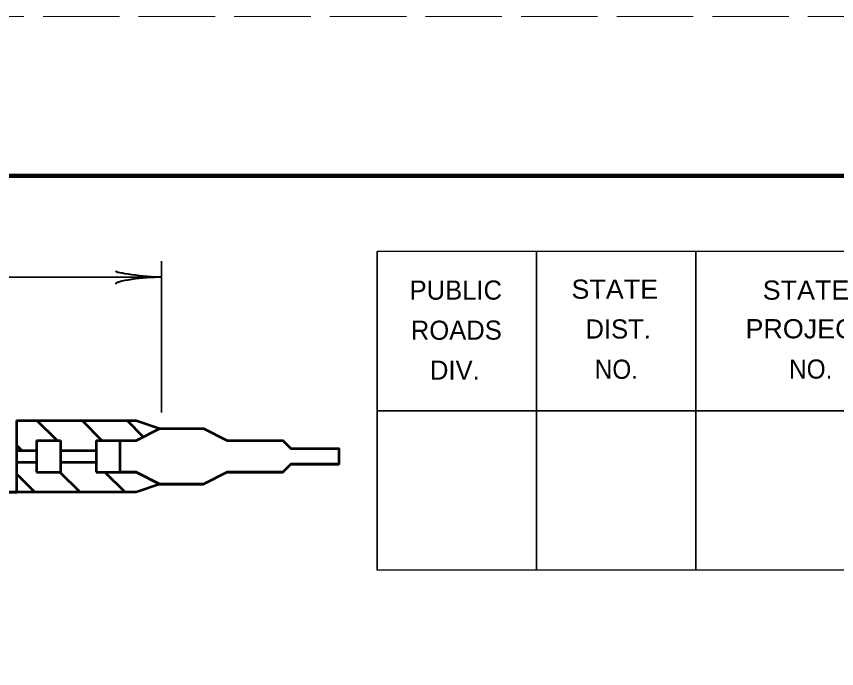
# Model space of a CAD drawing. Extents: x -1 to 679, y 0 to 440.
# Drawn here: x 531 to 582.5, y 399 to 439.9 of the extents above; entities that cross this region are included whole.
import ezdxf

# ---------------------------------------------------------------- set-up
doc = ezdxf.new("R2010")
doc.units = 0
doc.header["$LTSCALE"] = 0.8
doc.linetypes.add('LONG_DASHED', pattern=[7.5, 6, -1.5])
doc.layers.add('1', color=7, linetype='Continuous', lineweight=53)
doc.layers.add('61', color=7, linetype='Continuous', lineweight=35)

msp = doc.modelspace()

# ---------------------------------------------------------------- linework, layer by layer
at = {"layer": '1', "lineweight": 35}
for p, q in [((540.1397, 415.0423), (540.1397, 424.5423)), ((506.156, 423.5423), (540.1397, 423.5423))]:
    msp.add_line(p, q, dxfattribs=at)
at = {"layer": '1'}
for p, q in [((531.0403, 414.5423), (538.5534, 414.5423)), ((531.0497, 414.5423), (531.0497, 410.0423)), ((533.5727, 413.3044), (532.3348, 414.5423)), ((536.4132, 413.2923), (535.1632, 414.5423)), ((539.0078, 413.5261), (537.9916, 414.5423)), ((538.5534, 414.5423), (540.0372, 414.0423)), ((538.5534, 413.2982), (540.0372, 414.0423)), ((540.0372, 414.0423), (542.7872, 414.0423)), ((532.3034, 413.2982), (532.3034, 411.2982)), ((532.3034, 413.2982), (533.8034, 413.2982)), ((533.8034, 413.2982), (533.8034, 411.2982)), ((536.0534, 413.2982), (536.0534, 411.2982)), ((536.0534, 413.2982), (538.5534, 413.2982)), ((547.7709, 413.2982), (548.2709, 412.7982)), ((531.3755, 412.6732), (531.0481, 413.0006)), ((548.2709, 412.7982), (551.2709, 412.7982)), ((551.2709, 412.7982), (551.2709, 411.7982)), ((531.0497, 412.6732), (532.3034, 412.6732)), ((533.8034, 412.6732), (536.0534, 412.6732)), ((531.0497, 411.9232), (532.3034, 411.9232)), ((533.8034, 411.9232), (536.0534, 411.9232)), ((547.7709, 411.2982), (548.2709, 411.7982)), ((548.2709, 411.7982), (551.2709, 411.7982)), ((532.3034, 411.2982), (533.8034, 411.2982)), ((535.0358, 410.0423), (533.7726, 411.3055)), ((536.0534, 411.2982), (538.5534, 411.2982)), ((537.8643, 410.0423), (536.6142, 411.2923)), ((538.5534, 411.2982), (540.0372, 410.5423)), ((544.2709, 411.2982), (547.7709, 411.2982)), ((532.2073, 410.0423), (531.0571, 411.1927)), ((540.0372, 410.5423), (538.5534, 410.0423)), ((540.0372, 410.5423), (542.7872, 410.5423)), ((525.156, 410.0423), (531.0628, 410.0423)), ((538.5534, 410.0423), (531.0628, 410.0423))]:
    msp.add_line(p, q, dxfattribs=at)
msp.add_lwpolyline([(537.5534, 411.2982), (537.5534, 413.2982), (538.5534, 413.2982), (540.0372, 414.0423), (542.7872, 414.0423), (544.2709, 413.2982), (547.7709, 413.2982), (548.2709, 412.7982), (551.2709, 412.7982), (551.2709, 411.7982), (548.2709, 411.7982), (547.7709, 411.2982), (544.2709, 411.2982), (542.7872, 410.5423), (540.0372, 410.5423), (538.5534, 411.2982)], close=True, dxfattribs=at)
for points in [[(542.7872, 414.0423), (544.2709, 413.2982), (547.7709, 413.2982)], [(531.0628, 410.0423), (527.294, 410.0423), (527.294, 413.2981)]]:
    msp.add_lwpolyline(points, dxfattribs=at)
at = {"layer": '1', "lineweight": 40}
for centre, major_axis, ratio, start_param, end_param in [((539.0192, 423.7539), (1.7565, -0.1757), 0.07063, 3.1407148, 5.41811), ((539.0485, 423.266), (1.7857, 0.1562), 0.122415, 0.8963533, 3.1415927)]:
    msp.add_ellipse(centre, major_axis=major_axis, ratio=ratio, start_param=start_param, end_param=end_param, dxfattribs=at)
at = {"layer": '61', "linetype": 'LONG_DASHED', "lineweight": 13}
msp.add_line((-1.285, 439.9088), (678.735, 439.9088), dxfattribs=at)
at = {"layer": '61'}
for p, q in [((563.675, 425.1488), (563.675, 405.1488)), ((573.675, 425.1488), (573.675, 405.1488)), ((661.675, 415.1288), (553.655, 415.1488))]:
    msp.add_line(p, q, dxfattribs=at)
at = {"layer": '61', "lineweight": 158}
msp.add_lwpolyline([(667.755, 429.9088), (28.715, 429.9088), (28.715, 9.8888)], dxfattribs=at)
at = {"layer": '61'}
for points in [[(661.655, 425.1688), (553.675, 425.1488), (553.675, 405.1488)], [(661.655, 425.1688), (661.655, 405.1688), (553.675, 405.1488)]]:
    msp.add_lwpolyline(points, dxfattribs=at)

# ---------------------------------------------------------------- texts
for s, rotation, p in [('PUBLIC', 0.033, (555.715, 422.1288)), ('ROADS', 0.124, (555.795, 419.6088)), ('DIST.', 0.056, (566.755, 419.6888)), ('DIV.', 359.932, (556.995, 417.1088))]:
    msp.add_text(s, height=1.201, rotation=rotation, dxfattribs=at).set_placement(p)
for s, rotation, width, p in [('STATE', 0.059, 1.05, (565.875, 422.1888)), ('STATE', 0.059, 1.05, (577.875, 422.1288)), ('PROJECT', 359.908, 1.05, (576.795, 419.7088)), ('NO.', 359.852, 0.95, (567.335, 417.1688)), ('NO.', 0.225, 0.95, (579.535, 417.1688))]:
    msp.add_text(s, height=1.201, rotation=rotation, dxfattribs=dict(at, width=width)).set_placement(p)

doc.saveas('drawing.dxf')
